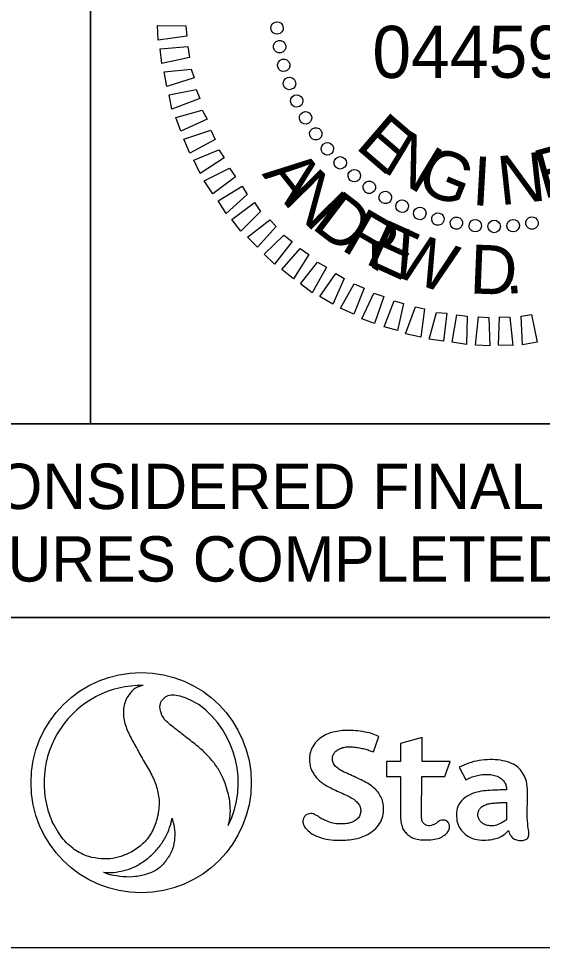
# Model space of a CAD drawing. Extents: x 2320980 to 2456309, y 595047 to 606177.
# Drawn here: x 2456020.37 to 2456033.07, y 597570.06 to 597592.89 of the extents above; entities that cross this region are included whole.
import ezdxf

# ---------------------------------------------------------------- set-up
doc = ezdxf.new("R2010")
doc.units = 0
for name, color, linetype in [('Default', 7, 'Continuous'), ('Scratch_Level_0', 7, 'Continuous'), ('Sheet Data Text CELL', 7, 'Continuous'), ('Sheet Plan CELL', 7, 'Continuous'), ('Sheet Sticker Exception Certification CELL', 7, 'Continuous')]:
    doc.layers.add(name, color=color, linetype=linetype)

msp = doc.modelspace()

# ---------------------------------------------------------------- linework, layer by layer
at = {"layer": 'Default'}
for p, q in [((2456026.634, 597592.653), (2456026.634, 597592.653)), ((2456026.634, 597592.653), (2456026.634, 597592.653)), ((2456026.705, 597592.212), (2456026.705, 597592.212)), ((2456026.705, 597592.212), (2456026.705, 597592.212)), ((2456026.799, 597591.75), (2456026.799, 597591.75)), ((2456026.799, 597591.75), (2456026.799, 597591.75)), ((2456026.933, 597591.31), (2456026.933, 597591.31)), ((2456026.933, 597591.31), (2456026.933, 597591.31)), ((2456027.11, 597590.882), (2456027.11, 597590.882)), ((2456027.11, 597590.882), (2456027.11, 597590.882)), ((2456027.328, 597590.486), (2456027.328, 597590.486)), ((2456027.328, 597590.486), (2456027.328, 597590.486)), ((2456027.577, 597590.09), (2456027.577, 597590.09)), ((2456027.577, 597590.09), (2456027.577, 597590.09)), ((2456027.848, 597589.727), (2456027.848, 597589.727)), ((2456027.848, 597589.727), (2456027.848, 597589.727)), ((2456028.17, 597589.385), (2456028.17, 597589.385)), ((2456028.17, 597589.385), (2456028.17, 597589.385)), ((2456028.492, 597589.075), (2456028.492, 597589.075)), ((2456028.492, 597589.075), (2456028.492, 597589.075)), ((2456028.876, 597588.798), (2456028.876, 597588.798)), ((2456028.876, 597588.798), (2456028.876, 597588.798)), ((2456029.261, 597588.541), (2456029.261, 597588.541)), ((2456029.261, 597588.541), (2456029.261, 597588.541)), ((2456029.675, 597588.329), (2456029.675, 597588.329)), ((2456029.675, 597588.329), (2456029.675, 597588.329)), ((2456030.089, 597588.147), (2456030.089, 597588.147)), ((2456030.089, 597588.147), (2456030.089, 597588.147)), ((2456030.545, 597588.019), (2456030.545, 597588.019)), ((2456030.545, 597588.019), (2456030.545, 597588.019)), ((2456030.989, 597587.932), (2456030.989, 597587.932)), ((2456030.989, 597587.932), (2456030.989, 597587.932)), ((2456031.443, 597587.867), (2456031.443, 597587.867)), ((2456031.443, 597587.867), (2456031.443, 597587.867)), ((2456031.907, 597587.844), (2456031.907, 597587.844)), ((2456031.907, 597587.844), (2456031.907, 597587.844)), ((2456032.37, 597587.863), (2456032.37, 597587.863)), ((2456032.37, 597587.863), (2456032.37, 597587.863)), ((2456032.822, 597587.935), (2456032.822, 597587.935)), ((2456032.822, 597587.935), (2456032.822, 597587.935))]:
    msp.add_line(p, q, dxfattribs=at)
for points in [[(2456024.446, 597592.464), (2456023.753, 597592.367), (2456023.736, 597592.725), (2456024.421, 597592.717)], [(2456024.509, 597591.949), (2456023.837, 597591.799), (2456023.799, 597592.157), (2456024.472, 597592.212)], [(2456024.624, 597591.457), (2456023.964, 597591.244), (2456023.894, 597591.601), (2456024.556, 597591.666)], [(2456024.759, 597590.953), (2456024.08, 597590.698), (2456024.02, 597591.044), (2456024.671, 597591.173)], [(2456024.938, 597590.451), (2456024.3, 597590.165), (2456024.178, 597590.49), (2456024.817, 597590.67)], [(2456025.136, 597589.959), (2456024.521, 597589.632), (2456024.378, 597589.966), (2456025.027, 597590.189)], [(2456025.355, 597589.511), (2456024.773, 597589.131), (2456024.619, 597589.455), (2456025.225, 597589.709)], [(2456025.627, 597589.053), (2456025.077, 597588.642), (2456024.871, 597588.954), (2456025.486, 597589.261)], [(2456025.91, 597588.626), (2456025.402, 597588.163), (2456025.206, 597588.475), (2456025.79, 597588.824)], [(2456026.233, 597588.211), (2456025.757, 597587.738), (2456025.542, 597588.019), (2456026.092, 597588.429)], [(2456026.619, 597587.849), (2456026.165, 597587.346), (2456025.918, 597587.594), (2456026.458, 597588.015)], [(2456027.005, 597587.488), (2456026.573, 597586.932), (2456026.327, 597587.18), (2456026.802, 597587.642)], [(2456027.411, 597587.169), (2456027.033, 597586.583), (2456026.754, 597586.809), (2456027.198, 597587.313)], [(2456027.838, 597586.861), (2456027.492, 597586.244), (2456027.204, 597586.459), (2456027.615, 597586.984)], [(2456028.265, 597586.585), (2456027.992, 597585.968), (2456027.673, 597586.152), (2456028.063, 597586.708)], [(2456028.754, 597586.352), (2456028.503, 597585.726), (2456028.173, 597585.867), (2456028.51, 597586.463)], [(2456029.232, 597586.15), (2456029.002, 597585.493), (2456028.694, 597585.613), (2456028.988, 597586.23)], [(2456029.709, 597585.98), (2456029.564, 597585.324), (2456029.235, 597585.413), (2456029.476, 597586.049)], [(2456030.217, 597585.853), (2456030.125, 597585.167), (2456029.754, 597585.243), (2456029.995, 597585.901)], [(2456030.756, 597585.747), (2456030.674, 597585.071), (2456030.326, 597585.118), (2456030.503, 597585.764)], [(2456031.253, 597585.672), (2456031.234, 597584.987), (2456030.885, 597585.044), (2456030.999, 597585.709)], [(2456031.78, 597585.64), (2456031.804, 597584.956), (2456031.456, 597584.97), (2456031.527, 597585.656)], [(2456032.285, 597585.649), (2456032.361, 597584.967), (2456032.014, 597584.97), (2456032.033, 597585.656)], [(2456032.811, 597585.712), (2456032.95, 597585.041), (2456032.593, 597584.981), (2456032.559, 597585.676)]]:
    msp.add_lwpolyline(points, close=True, dxfattribs=at)
for centre, major_axis in [((2456026.638, 597592.665), (-0.151, -0.013)), ((2456026.699, 597592.209), (-0.149, -0.027)), ((2456026.799, 597591.759), (-0.146, -0.039)), ((2456026.938, 597591.319), (-0.142, -0.052)), ((2456027.115, 597590.894), (-0.137, -0.064)), ((2456027.329, 597590.485), (-0.131, -0.076)), ((2456027.577, 597590.097), (-0.124, -0.087)), ((2456027.858, 597589.732), (-0.116, -0.098)), ((2456028.17, 597589.393), (-0.107, -0.107)), ((2456028.51, 597589.082), (-0.097, -0.116)), ((2456028.876, 597588.802), (-0.087, -0.124)), ((2456029.265, 597588.555), (-0.076, -0.131)), ((2456029.674, 597588.342), (-0.064, -0.138)), ((2456030.1, 597588.167), (-0.052, -0.143)), ((2456030.54, 597588.029), (-0.039, -0.147)), ((2456030.99, 597587.93), (-0.026, -0.149)), ((2456031.447, 597587.87), (-0.013, -0.151)), ((2456032.368, 597587.871), (0.013, -0.151)), ((2456032.824, 597587.932), (0.027, -0.149)), ((2456031.907, 597587.851), (0, -0.152))]:
    msp.add_ellipse(centre, major_axis=major_axis, ratio=0.999708, dxfattribs=at)
at = {"layer": 'Scratch_Level_0'}
msp.add_lwpolyline([(2456019.333, 597578.364), (2456042.107, 597578.366), (2456042.108, 597570.357), (2456019.334, 597570.354)], close=True, dxfattribs=at)
at = {"layer": 'Sheet Data Text CELL'}
for p, q in [((2456028.975, 597575.107), (2456029.105, 597575.479)), ((2456030.155, 597575.457), (2456029.629, 597575.31)), ((2456030.155, 597574.872), (2456030.155, 597575.457)), ((2456029.629, 597575.31), (2456029.629, 597574.873)), ((2456029.629, 597574.873), (2456029.295, 597574.873)), ((2456029.295, 597574.873), (2456029.295, 597574.506)), ((2456030.836, 597574.873), (2456030.155, 597574.872)), ((2456030.709, 597574.506), (2456030.836, 597574.873)), ((2456031.056, 597574.739), (2456031.216, 597574.429)), ((2456029.295, 597574.506), (2456029.633, 597574.506)), ((2456030.145, 597573.581), (2456030.152, 597574.506)), ((2456030.152, 597574.506), (2456030.709, 597574.506)), ((2456032.205, 597573.878), (2456032.206, 597573.463))]:
    msp.add_line(p, q, dxfattribs=at)
for points in [[(2456023.389, 597576.716), (2456023.389, 597576.716)], [(2456024.742, 597576.253), (2456024.742, 597576.252)]]:
    msp.add_lwpolyline(points, dxfattribs=at)
msp.add_circle((2456023.338, 597574.36), 2.673, dxfattribs=at)
for start, end in [(88.7738, 203.6916), (88.7673, 88.7738), (333.7886, 53.4398), (247.1256, 251.4651)]:
    msp.add_arc((2456023.338, 597574.36), 2.357, start, end, dxfattribs=at)
for points, degree in [([(2456023.389, 597576.716), (2456023.332, 597576.704), (2456023.198, 597576.675), (2456023.023, 597576.497), (2456022.893, 597576.204), (2456022.91, 597575.875), (2456023.026, 597575.556), (2456023.202, 597575.248), (2456023.384, 597574.906), (2456023.586, 597574.584), (2456023.726, 597574.257), (2456023.792, 597573.902), (2456023.749, 597573.545), (2456023.645, 597573.218), (2456023.444, 597572.921), (2456023.18, 597572.71), (2456022.904, 597572.587), (2456022.654, 597572.509), (2456022.375, 597572.509), (2456022.065, 597572.553), (2456021.759, 597572.693), (2456021.433, 597572.969), (2456021.276, 597573.24), (2456021.18, 597573.413)], 3), ([(2456023.389, 597576.716), (2456023.389, 597576.716), (2456023.389, 597576.716), (2456023.389, 597576.716)], 2), ([(2456025.452, 597573.319), (2456025.473, 597573.401), (2456025.508, 597573.556), (2456025.501, 597573.806), (2456025.477, 597574.024), (2456025.413, 597574.227), (2456025.337, 597574.462), (2456025.204, 597574.718), (2456025.014, 597574.958), (2456024.766, 597575.211), (2456024.456, 597575.436), (2456024.137, 597575.696), (2456023.881, 597575.889), (2456023.791, 597576.115), (2456023.79, 597576.286), (2456023.875, 597576.403), (2456023.988, 597576.484), (2456024.139, 597576.497), (2456024.317, 597576.463), (2456024.523, 597576.376), (2456024.665, 597576.296), (2456024.742, 597576.253)], 3), ([(2456029.105, 597575.479), (2456029.082, 597575.491), (2456028.978, 597575.54), (2456028.78, 597575.593), (2456028.537, 597575.623), (2456028.316, 597575.633), (2456028.131, 597575.615), (2456027.955, 597575.579), (2456027.785, 597575.511), (2456027.621, 597575.399), (2456027.503, 597575.248), (2456027.436, 597575.096), (2456027.421, 597574.954), (2456027.428, 597574.824), (2456027.456, 597574.699), (2456027.509, 597574.596), (2456027.573, 597574.502), (2456027.652, 597574.418), (2456027.748, 597574.341), (2456027.866, 597574.269), (2456028.013, 597574.194), (2456028.175, 597574.119), (2456028.34, 597574.049), (2456028.476, 597573.979), (2456028.576, 597573.894), (2456028.645, 597573.814), (2456028.669, 597573.716), (2456028.666, 597573.623), (2456028.628, 597573.521), (2456028.543, 597573.436), (2456028.408, 597573.377), (2456028.248, 597573.354), (2456028.07, 597573.362), (2456027.913, 597573.394), (2456027.786, 597573.457), (2456027.683, 597573.499), (2456027.614, 597573.564), (2456027.548, 597573.589), (2456027.488, 597573.616), (2456027.423, 597573.611), (2456027.358, 597573.591), (2456027.303, 597573.544), (2456027.267, 597573.475), (2456027.264, 597573.4), (2456027.275, 597573.327), (2456027.333, 597573.249), (2456027.445, 597573.137), (2456027.643, 597573.039), (2456027.888, 597572.974), (2456028.137, 597572.961), (2456028.351, 597572.967), (2456028.538, 597572.991), (2456028.702, 597573.041), (2456028.873, 597573.119), (2456029.037, 597573.247), (2456029.164, 597573.407), (2456029.218, 597573.596), (2456029.225, 597573.767), (2456029.204, 597573.921), (2456029.143, 597574.045), (2456029.07, 597574.168), (2456028.942, 597574.273), (2456028.797, 597574.37), (2456028.637, 597574.447), (2456028.464, 597574.529), (2456028.284, 597574.606), (2456028.131, 597574.686), (2456028.028, 597574.78), (2456027.984, 597574.87), (2456027.976, 597574.966), (2456028.004, 597575.052), (2456028.063, 597575.128), (2456028.145, 597575.182), (2456028.253, 597575.222), (2456028.382, 597575.231), (2456028.51, 597575.226), (2456028.637, 597575.206), (2456028.76, 597575.18), (2456028.875, 597575.145), (2456028.944, 597575.119), (2456028.975, 597575.107)], 3), ([(2456032.257, 597573.203), (2456032.258, 597573.185), (2456032.262, 597573.142), (2456032.305, 597573.077), (2456032.367, 597573.006), (2456032.479, 597572.953), (2456032.597, 597572.957), (2456032.707, 597572.982), (2456032.75, 597573.068), (2456032.752, 597573.156), (2456032.727, 597573.273), (2456032.7, 597573.594), (2456032.72, 597573.935), (2456032.714, 597574.302), (2456032.672, 597574.48), (2456032.572, 597574.641), (2456032.464, 597574.764), (2456032.286, 597574.854), (2456032.066, 597574.911), (2456031.805, 597574.927), (2456031.541, 597574.901), (2456031.287, 597574.842), (2456031.131, 597574.772), (2456031.056, 597574.739)], 3), ([(2456031.216, 597574.429), (2456031.24, 597574.442), (2456031.313, 597574.481), (2456031.432, 597574.517), (2456031.576, 597574.554), (2456031.712, 597574.564), (2456031.854, 597574.558), (2456031.982, 597574.518), (2456032.093, 597574.455), (2456032.171, 597574.361), (2456032.204, 597574.267), (2456032.204, 597574.208), (2456032.204, 597574.188)], 3), ([(2456029.633, 597574.506), (2456029.631, 597574.179), (2456029.63, 597573.834), (2456029.634, 597573.449), (2456029.651, 597573.357), (2456029.687, 597573.231), (2456029.759, 597573.146), (2456029.831, 597573.079), (2456029.908, 597573.028), (2456030.03, 597572.985), (2456030.198, 597572.967), (2456030.372, 597572.974), (2456030.546, 597572.998), (2456030.678, 597573.065), (2456030.775, 597573.144), (2456030.82, 597573.234), (2456030.825, 597573.313), (2456030.811, 597573.379), (2456030.776, 597573.418), (2456030.734, 597573.443), (2456030.685, 597573.452), (2456030.633, 597573.453), (2456030.58, 597573.44), (2456030.533, 597573.402), (2456030.48, 597573.362), (2456030.415, 597573.334), (2456030.346, 597573.312), (2456030.274, 597573.32), (2456030.212, 597573.353), (2456030.164, 597573.402), (2456030.143, 597573.485), (2456030.144, 597573.544), (2456030.145, 597573.581)], 3), ([(2456032.204, 597574.188), (2456032.17, 597574.187), (2456032.06, 597574.185), (2456031.869, 597574.176), (2456031.642, 597574.165), (2456031.43, 597574.118), (2456031.234, 597574.036), (2456031.063, 597573.889), (2456030.983, 597573.682), (2456030.994, 597573.486), (2456031.026, 597573.317), (2456031.128, 597573.176), (2456031.276, 597573.046), (2456031.488, 597572.966), (2456031.708, 597572.963), (2456031.912, 597572.99), (2456032.067, 597573.044), (2456032.182, 597573.123), (2456032.23, 597573.174), (2456032.257, 597573.203)], 3), ([(2456032.206, 597573.463), (2456032.193, 597573.453), (2456032.144, 597573.415), (2456032.055, 597573.367), (2456031.93, 597573.316), (2456031.797, 597573.307), (2456031.682, 597573.338), (2456031.602, 597573.389), (2456031.55, 597573.451), (2456031.515, 597573.524), (2456031.51, 597573.604), (2456031.525, 597573.683), (2456031.572, 597573.757), (2456031.653, 597573.806), (2456031.749, 597573.848), (2456031.876, 597573.866), (2456032.006, 597573.873), (2456032.121, 597573.88), (2456032.181, 597573.879), (2456032.205, 597573.878)], 3), ([(2456022.422, 597572.188), (2456022.48, 597572.182), (2456022.616, 597572.169), (2456022.85, 597572.214), (2456023.111, 597572.276), (2456023.346, 597572.412), (2456023.562, 597572.564), (2456023.765, 597572.782), (2456023.933, 597573.025), (2456024.04, 597573.277), (2456024.072, 597573.426), (2456024.088, 597573.497)], 3), ([(2456024.088, 597573.497), (2456024.105, 597573.437), (2456024.149, 597573.284), (2456024.16, 597573.028), (2456024.116, 597572.751), (2456023.973, 597572.499), (2456023.781, 597572.266), (2456023.501, 597572.139), (2456023.204, 597572.072), (2456022.898, 597572.067), (2456022.689, 597572.106), (2456022.589, 597572.125)], 3)]:
    msp.add_open_spline(points, degree=degree, dxfattribs=at)
at = {"layer": 'Sheet Plan CELL'}
msp.add_line((2456022.107, 597605.564), (2456022.109, 597583.071), dxfattribs=at)
for points in [[(2455742.104, 597403.076), (2455742.099, 597613.071), (2456002.097, 597613.079), (2456002.099, 597583.066), (2456042.107, 597583.064), (2456042.107, 597403.076)], [(2456002.097, 597605.564), (2456022.107, 597605.564), (2456022.107, 597583.061), (2456002.099, 597583.066)], [(2456022.107, 597605.564), (2456042.104, 597605.566), (2456042.107, 597583.064), (2456022.107, 597583.061)]]:
    msp.add_lwpolyline(points, close=True, dxfattribs=at)
at = {"layer": 'Sheet Sticker Exception Certification CELL'}
for p, q in [((2456002.099, 597583.066), (2456042.107, 597583.066)), ((2456002.099, 597583.066), (2456042.107, 597583.066)), ((2456042.107, 597578.366), (2456002.099, 597578.366)), ((2456042.107, 597578.366), (2456002.099, 597578.366))]:
    msp.add_line(p, q, dxfattribs=at)

# ---------------------------------------------------------------- texts
at = {"layer": 'Default'}
for s, height, rotation, p in [('044590', 1.2638, 0.081, (2456028.951, 597591.451)), ('E', 1.188, 319.3578, (2456028.51, 597589.771)), ('N', 1.188, 328.7149, (2456029.152, 597589.214)), ('E', 1.188, 15.4927, (2456033.095, 597588.509)), ('G', 1.188, 338.0712, (2456029.962, 597588.755)), ('N', 1.188, 6.1373, (2456032.055, 597588.363)), ('A', 1.188, 308.1238, (2456026.255, 597589.117)), ('I', 1.188, 356.7822, (2456031.349, 597588.371)), ('N', 1.188, 314.6899, (2456026.751, 597588.497)), ('D', 1.188, 322.6565, (2456027.443, 597587.828)), ('R', 1.188, 329.9918, (2456028.156, 597587.302)), ('E', 1.188, 335.5478, (2456028.738, 597586.967)), ('W', 1.188, 340.8282, (2456029.319, 597586.702)), ('D', 1.188, 357.7142, (2456031.298, 597586.229)), ('.', 1.188, 5.0495, (2456032.184, 597586.208))]:
    msp.add_text(s, height=height, rotation=rotation, dxfattribs=at).set_placement(p)
at = {"layer": 'Sheet Sticker Exception Certification CELL'}
for s, p in [('DOCUMENT NOT CONSIDERED FINAL', (2456006.313, 597580.997)), ('DOCUMENT NOT CONSIDERED FINAL', (2456006.313, 597580.997)), ('UNLESS ALL SIGNATURES COMPLETED', (2456005.299, 597579.237)), ('UNLESS ALL SIGNATURES COMPLETED', (2456005.299, 597579.237))]:
    msp.add_text(s, height=1.1, dxfattribs=at).set_placement(p)

doc.saveas('drawing.dxf')
